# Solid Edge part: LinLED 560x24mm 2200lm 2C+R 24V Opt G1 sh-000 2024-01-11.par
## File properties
Author: robert.pupel
Template: iso metric part.par
Last saved by: robert.pupel
Revision: 3
Application: Solid Edge
Gęstość: 0.000 kg/m^3
Dokładność: 0.990
Username: robert.pupel
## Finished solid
Body 1: solid body, 2137 faces, 5506 edges, 3552 vertices.
  Faces by surface: plane 1527, cylinder 294, torus 128, cone 100, spline 52, sphere 32, swept 4
  Edges by curve: line 4102, curve on surface 752, circle 352, spline 168, ellipse 132
Bounding box of the edges (mm; curved faces can reach further): 559.600 x 4.450 x 24.000, from (-279.8, -3.45, -12) to (279.8, 1, 12).
Cylindrical faces by radius (mm): R0.2 x92, R0.2169 x12, R0.25 x36, R0.3373 x12, R0.4 x16, R0.4006 x4, R0.4008 x4, R0.525 x4, R0.6 x40, R1 x20, R1.1 x8, R1.1989 x4, R1.199 x4, R1.2 x20, R1.5309 x2, R1.5312 x2, R1.7414 x2, R1.7423 x2, R2.15 x10
Conical faces (half-angle, radius in mm at the cone's reference point): 0.398 deg R1.1964 x4, 0.4493 deg R1.1964 x4, 0.4746 deg R1.1948 x4, 0.4758 deg R1.1948 x4, 0.5 deg R0.5056 x8, 0.5 deg R1.0082 x8, 1 deg R0.5511 x4, 10 deg R0.2132 x8, 10 deg R0.4132 x8, 16.0099 deg R1.1053 x4, 16.1249 deg R1.1279 x4, 18.8604 deg R1.0669 x8, 19.5041 deg R0.5138 x4, 19.8244 deg R0.5099 x4, 27.363 deg R0.6214 x4, 40.6434 deg R0.5161 x4, 43.3309 deg R0.4892 x4, 45 deg R0.575 x4, 45 deg R0.625 x8
Toroidal faces (ring radius, tube radius in mm): R0.0958 r0.3997 x8, R0.1076 r0.4 x4, R0.1101 r0.4001 x4, R0.1217 r0.4 x4, R0.1234 r0.4 x4, R0.1626 r0.228 x4, R0.1634 r0.2287 x4, R0.3287 r0.2001 x4, R0.3684 r0.2151 x4, R0.3703 r0.4 x4, R0.3818 r0.2 x8, R0.4166 r0.3983 x4, R0.5981 r0.197 x4, R0.5982 r0.197 x4, R0.6009 r0.3968 x4, R0.6009 r0.3969 x4, R0.6227 r0.2 x4, R0.6235 r0.2 x4, R0.8 r0.2 x8, R0.8522 r0.3 x4, R0.9002 r0.2 x4, R0.9018 r0.2 x4, R0.9197 r0.223 x4, R0.9365 r0.2 x4, R0.9663 r0.2263 x4, R0.9665 r0.2263 x4, R1.429 r1.2 x4, R1.8741 r0.2175 x4, R1.9007 r0.2 x4
Spherical faces by radius (mm): R0.2 x24, R0.6 x8
Planar faces by outward normal: +x 176, +y 17, +z 188, -x 176, -y 260, -z 194, oblique 516
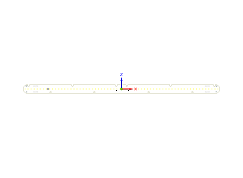
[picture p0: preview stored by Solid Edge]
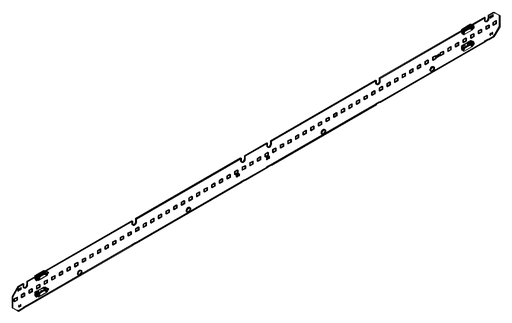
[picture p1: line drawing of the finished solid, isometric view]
